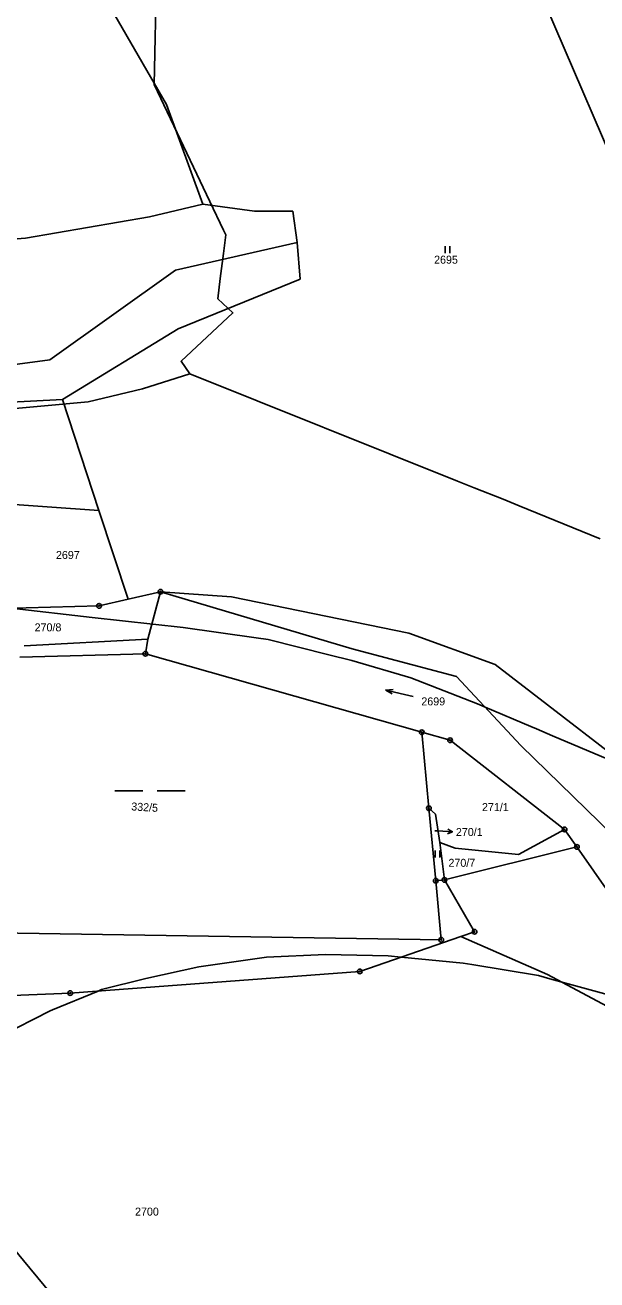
# Model space of a CAD drawing. Extents: x -546762 to -540209, y -1046851 to -1035694.
# Drawn here: x -542228.7 to -542107.3, y -1038969.2 to -1038702.7 of the extents above; entities that cross this region are included whole.
import ezdxf

# ---------------------------------------------------------------- set-up
doc = ezdxf.new("R2010")
doc.units = 0
for name, color, linetype in [('Vrstva 1', 7, 'Continuous'), ('Vrstva 16', 7, 'Continuous'), ('Vrstva 18', 7, 'Continuous'), ('Vrstva 24', 7, 'Continuous'), ('Vrstva 25', 7, 'Continuous'), ('Vrstva 52', 7, 'Continuous')]:
    doc.layers.add(name, color=color, linetype=linetype)

msp = doc.modelspace()

# ---------------------------------------------------------------- linework, layer by layer
at = {"layer": 'Vrstva 1'}
for p, q in [((-542142.96, -1038869.01), (-542144.49, -1038852.87)), ((-542141.51, -1038884.39), (-542142.96, -1038869.01)), ((-542142.96, -1038869.01), (-542141.58, -1038870.26)), ((-542139.67, -1038884.22), (-542140.63, -1038876.25)), ((-542141.51, -1038884.39), (-542139.67, -1038884.22)), ((-542140.34, -1038896.94), (-542141.51, -1038884.39)), ((-542273.83, -1038894.83), (-542140.34, -1038896.94))]:
    msp.add_line(p, q, dxfattribs=at)
for points in [[(-542102.16, -1038735.71), (-542130.32, -1038670.22)], [(-542198.68, -1038719.56), (-542219.88, -1038682.9)], [(-542190.96, -1038740.77), (-542198.68, -1038719.56)], [(-542202.31, -1038743.42), (-542190.96, -1038740.77)], [(-542190.96, -1038740.77), (-542179.98, -1038742.22)], [(-542228.63, -1038747.93), (-542202.31, -1038743.42)], [(-542179.98, -1038742.22), (-542171.86, -1038742.26)], [(-542171.86, -1038742.26), (-542170.91, -1038748.88)], [(-542282.38, -1038752.22), (-542228.63, -1038747.93)], [(-542196.8, -1038754.78), (-542170.91, -1038748.88)], [(-542170.91, -1038748.88), (-542170.32, -1038756.63)], [(-542223.47, -1038773.81), (-542196.8, -1038754.78)], [(-542170.32, -1038756.63), (-542196.2, -1038767.2)], [(-542196.2, -1038767.2), (-542220.79, -1038782.25)], [(-542262.69, -1038779.03), (-542223.47, -1038773.81)], [(-542258.9, -1038784.22), (-542220.79, -1038782.25)], [(-542220.79, -1038782.25), (-542213.03, -1038805.77)], [(-542213.03, -1038805.77), (-542271.99, -1038801.64)], [(-542206.82, -1038824.6), (-542213.03, -1038805.77)], [(-542199.99, -1038823.03), (-542206.82, -1038824.6)], [(-542199.99, -1038823.03), (-542202.62, -1038833.12)], [(-542184.85, -1038824.12), (-542199.99, -1038823.03)], [(-542159.24, -1038835.18), (-542199.99, -1038823.03)], [(-542233.65, -1038826.6), (-542213.02, -1038826.03)], [(-542206.82, -1038824.6), (-542213.02, -1038826.03)], [(-542147.19, -1038831.83), (-542184.85, -1038824.12)], [(-542228.9, -1038834.54), (-542202.62, -1038833.12)], [(-542202.62, -1038833.12), (-542203.18, -1038836.22)], [(-542128.86, -1038838.49), (-542147.19, -1038831.83)], [(-542229.87, -1038836.96), (-542203.18, -1038836.22)], [(-542203.18, -1038836.22), (-542144.49, -1038852.87)], [(-542137.09, -1038841.03), (-542159.24, -1038835.18)], [(-542092.18, -1038866.82), (-542128.86, -1038838.49)], [(-542123.43, -1038855.68), (-542137.09, -1038841.03)], [(-542144.49, -1038852.87), (-542138.45, -1038854.58)], [(-542138.45, -1038854.58), (-542114.16, -1038873.52)], [(-542101.21, -1038877.36), (-542123.43, -1038855.68)], [(-542141.58, -1038870.26), (-542140.63, -1038876.25)], [(-542123.95, -1038878.82), (-542114.16, -1038873.52)], [(-542114.16, -1038873.52), (-542111.53, -1038877.23)], [(-542137.41, -1038877.47), (-542140.63, -1038876.25)], [(-542111.53, -1038877.23), (-542139.67, -1038884.22)], [(-542123.95, -1038878.82), (-542137.41, -1038877.47)], [(-542111.53, -1038877.23), (-542104.32, -1038887.52)], [(-542139.67, -1038884.22), (-542133.25, -1038895.25)], [(-542136.2, -1038896.27), (-542133.25, -1038895.25)], [(-542157.65, -1038903.67), (-542136.2, -1038896.27)], [(-542136.2, -1038896.27), (-542117.78, -1038904.31)], [(-542157.65, -1038903.67), (-542219.13, -1038908.26)], [(-542117.78, -1038904.31), (-542044.91, -1038943.18)], [(-542219.13, -1038908.26), (-542273.49, -1038910.46)]]:
    msp.add_lwpolyline(points, dxfattribs=at)
at = {"layer": 'Vrstva 16'}
msp.add_line((-542140.97, -1038873.83), (-542137.98, -1038874.01), dxfattribs=at)
for points in [[(-542141.7, -1038873.78), (-542140.97, -1038873.83)], [(-542138.94, -1038873.45), (-542137.98, -1038874.01), (-542139, -1038874.45)]]:
    msp.add_lwpolyline(points, dxfattribs=at)
at = {"layer": 'Vrstva 24'}
for centre, radius in [((-542199.99, -1038823.03), 0.5), ((-542199.99, -1038823.03), 0.1), ((-542213.02, -1038826.03), 0.5), ((-542213.02, -1038826.03), 0.1), ((-542203.18, -1038836.22), 0.5), ((-542203.18, -1038836.22), 0.1), ((-542144.49, -1038852.87), 0.5), ((-542144.49, -1038852.87), 0.1), ((-542138.45, -1038854.58), 0.5), ((-542138.45, -1038854.58), 0.1), ((-542142.96, -1038869.01), 0.5), ((-542142.96, -1038869.01), 0.1), ((-542114.16, -1038873.52), 0.5), ((-542114.16, -1038873.52), 0.1), ((-542111.53, -1038877.23), 0.5), ((-542111.53, -1038877.23), 0.1), ((-542141.51, -1038884.39), 0.5), ((-542141.51, -1038884.39), 0.1), ((-542139.67, -1038884.22), 0.5), ((-542139.67, -1038884.22), 0.1), ((-542133.25, -1038895.25), 0.5), ((-542133.25, -1038895.25), 0.1), ((-542140.34, -1038896.94), 0.5), ((-542140.34, -1038896.94), 0.1), ((-542157.65, -1038903.67), 0.5), ((-542157.65, -1038903.67), 0.1), ((-542219.13, -1038908.26), 0.5), ((-542219.13, -1038908.26), 0.1)]:
    msp.add_circle(centre, radius, dxfattribs=at)
at = {"layer": 'Vrstva 25'}
for p, q in [((-542139.51, -1038751.17), (-542139.51, -1038749.67)), ((-542138.51, -1038751.17), (-542138.51, -1038749.67)), ((-542209.69, -1038865.29), (-542203.69, -1038865.29)), ((-542200.69, -1038865.29), (-542194.69, -1038865.29)), ((-542141.65, -1038879.46), (-542141.65, -1038877.96)), ((-542140.65, -1038879.46), (-542140.65, -1038877.96))]:
    msp.add_line(p, q, dxfattribs=at)
for points in [[(-542152.12, -1038843.91), (-542150.54, -1038843.77)], [(-542146.28, -1038845.29), (-542152.12, -1038843.91), (-542150.77, -1038844.74)]]:
    msp.add_lwpolyline(points, dxfattribs=at)
at = {"layer": 'Vrstva 52'}
for points in [[(-542200.33, -1038668.82), (-542201.33, -1038715.33), (-542189.48, -1038740.2), (-542186.59, -1038746.26), (-542186.12, -1038747.25), (-542186.61, -1038751.22), (-542187.27, -1038756.5), (-542187.81, -1038760.83), (-542184.6, -1038763.83), (-542195.59, -1038774.11), (-542193.74, -1038776.8)], [(-542215.35, -1038782.74), (-542236.28, -1038784.61), (-542259.78, -1038780.72), (-542284.83, -1038753.92)], [(-542193.74, -1038776.8), (-542203.79, -1038779.92), (-542215.35, -1038782.74)], [(-542193.74, -1038776.8), (-542136.9, -1038799.53), (-542133.38, -1038800.94), (-542127.22, -1038803.41), (-542123.76, -1038804.79), (-542106.58, -1038811.81)], [(-542104.97, -1038858.58), (-542116.73, -1038853.61), (-542120.13, -1038852.16), (-542121.34, -1038851.64), (-542130.98, -1038847.53), (-542132.67, -1038846.81), (-542146.79, -1038841.32), (-542159.34, -1038837.66), (-542164.18, -1038836.45), (-542177.11, -1038833.21), (-542179.63, -1038832.84), (-542195.15, -1038830.6), (-542214.49, -1038828.51), (-542231.66, -1038826.54), (-542233.45, -1038826.34), (-542254.68, -1038823.91), (-542271.67, -1038821.56), (-542279.77, -1038820.78), (-542281.32, -1038820.59)], [(-542255.93, -1038932.48), (-542250.1, -1038928.15), (-542242.63, -1038922.92), (-542233.97, -1038917.39), (-542223.36, -1038912.01), (-542222.9, -1038911.82), (-542213.18, -1038907.82), (-542212.46, -1038907.52), (-542203.05, -1038905.13), (-542191.85, -1038902.7), (-542177.47, -1038900.61), (-542164.92, -1038900.09), (-542151.59, -1038900.35), (-542148.82, -1038900.62), (-542140.77, -1038901.41), (-542135.65, -1038901.92), (-542133.83, -1038902.22), (-542119.7, -1038904.53), (-542117.27, -1038905.2), (-542101.67, -1038909.5)], [(-542168.66, -1039043.38), (-542178.1, -1039029.62), (-542188.82, -1039014.72), (-542195.26, -1039006.35), (-542197.77, -1039003.09), (-542199.28, -1039001.12), (-542212.87, -1038984.64), (-542229.08, -1038965.03), (-542255.93, -1038932.48)]]:
    msp.add_lwpolyline(points, dxfattribs=at)

# ---------------------------------------------------------------- texts
at = {"layer": 'Vrstva 16'}
msp.add_text('270/1', height=1.7, dxfattribs=at).set_placement((-542137.23, -1038874.91))
at = {"layer": 'Vrstva 18'}
for s, height, p in [('2695', 1.7, (-542141.86, -1038753.38)), ('2697', 1.7, (-542222.17, -1038816.08)), ('270/8', 1.7, (-542226.7, -1038831.45)), ('2699', 1.7, (-542144.57, -1038847.17)), ('271/1', 1.7, (-542131.69, -1038869.61)), ('270/1', 0.1, (-542141.7, -1038873.78)), ('270/7', 1.7, (-542138.81, -1038881.45)), ('2700', 1.7, (-542205.37, -1038955.51))]:
    msp.add_text(s, height=height, dxfattribs=at).set_placement(p)
msp.add_text('332/5', height=1.7, rotation=356.63, dxfattribs=at).set_placement((-542206.22, -1038869.46))

doc.saveas('drawing.dxf')
